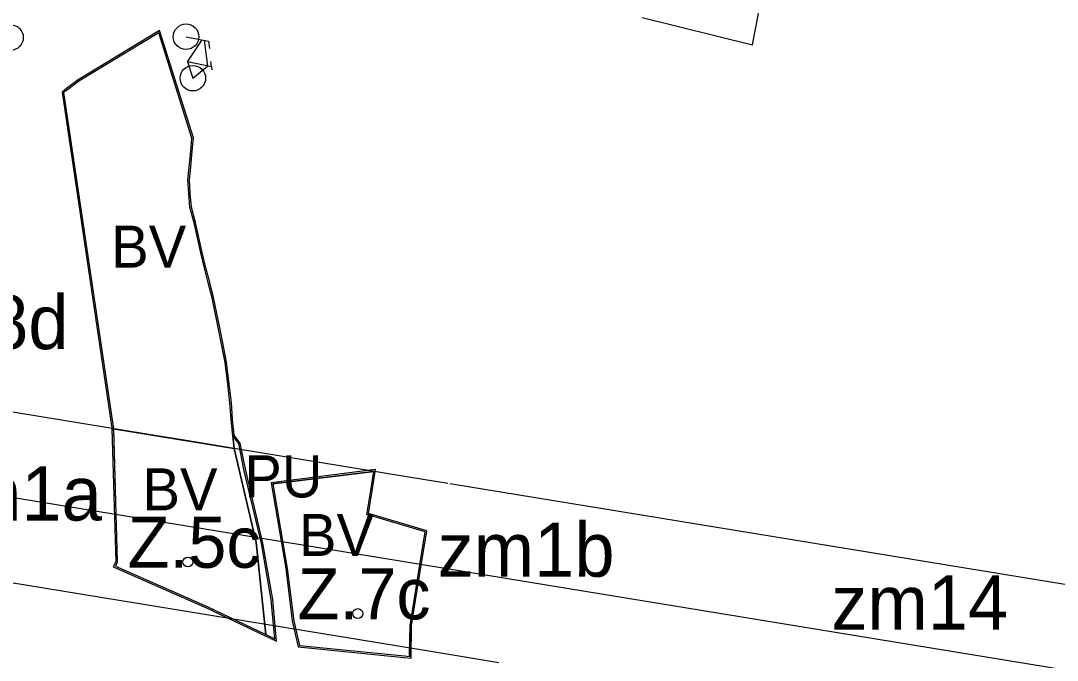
# Model space of a CAD drawing. Extents: x -555070 to -553076, y -1186731 to -1182766.
# Drawn here: x -554414.1 to -554069.4, y -1185567.7 to -1185354.8 of the extents above; entities that cross this region are included whole.
import ezdxf

# ---------------------------------------------------------------- set-up
doc = ezdxf.new("R2010")
doc.units = 0
for name, color, linetype in [('CYKLISTI_stav', 7, 'Continuous'), ('HRANICE_ZMENY_DO_KOO', 7, 'Continuous'), ('Level 10', 7, 'Continuous'), ('Level 13', 7, 'Continuous'), ('Level 29', 7, 'Continuous'), ('Level 4', 7, 'Continuous'), ('Level 46', 7, 'Continuous'), ('Level 52', 7, 'Continuous'), ('Level 56', 7, 'Continuous'), ('Level 58', 7, 'Continuous'), ('Level 59', 7, 'Continuous'), ('Level 63', 7, 'Continuous'), ('navrh_BV', 7, 'Continuous'), ('OBRYS_PLOCH', 7, 'Continuous'), ('stav_BV', 7, 'Continuous'), ('stav_PU', 7, 'Continuous'), ('ZU_plocha_aktualizace', 7, 'Continuous')]:
    doc.layers.add(name, color=color, linetype=linetype)

msp = doc.modelspace()

# ---------------------------------------------------------------- linework, layer by layer
at = {"layer": 'CYKLISTI_stav'}
msp.add_circle((-554417.54, -1185360.43), 4.25, dxfattribs=at)
at = {"layer": 'HRANICE_ZMENY_DO_KOO'}
for points in [[(-554343.11, -1185492.8), (-554343.66, -1185487.59), (-554344.1, -1185481.93), (-554344.79, -1185475.68), (-554345.66, -1185468.47), (-554347.53, -1185459.09), (-554350.01, -1185446.95), (-554351.29, -1185441.91), (-554352.54, -1185437.02), (-554353.81, -1185431.99), (-554355.99, -1185421.94), (-554357.37, -1185416.93), (-554357.74, -1185412.35), (-554358.05, -1185407.81), (-554357.6, -1185403.61), (-554357.23, -1185399.44), (-554356.73, -1185393.81), (-554367.98, -1185358.13), (-554395.09, -1185374.54), (-554398.94, -1185377.42), (-554400.4, -1185378.56), (-554383.76, -1185491.04)], [(-554383.82, -1185490.62), (-554382.57, -1185534.87), (-554383.35, -1185536.55), (-554352.18, -1185550.34), (-554329.03, -1185561.34), (-554330.35, -1185547.44), (-554333.58, -1185528.65), (-554339.41, -1185504.09), (-554341.19, -1185495.37), (-554343.11, -1185492.81)], [(-554383.68, -1185490.55), (-554343.14, -1185497.2), (-554343.59, -1185493)]]:
    msp.add_lwpolyline(points, dxfattribs=at)
msp.add_lwpolyline([(-554286.57, -1185566.73), (-554284.33, -1185566.95), (-554284.18, -1185556.14), (-554281.38, -1185538.8), (-554279.08, -1185524.56), (-554298.45, -1185518.79), (-554297.24, -1185511.26), (-554296.1, -1185504.23), (-554330.84, -1185508.57), (-554326.03, -1185537.16), (-554323.85, -1185554.59), (-554321.88, -1185563.24)], close=True, dxfattribs=at)
at = {"layer": 'Level 13'}
for p, q in [((-554207.47, -1185353.77), (-554170.79, -1185362.9)), ((-554368.27, -1185358.89), (-554394.81, -1185374.96)), ((-554357.24, -1185393.87), (-554368.27, -1185358.89)), ((-554170.79, -1185362.9), (-554170.79, -1185362.9)), ((-554394.81, -1185374.96), (-554398.64, -1185377.82)), ((-554398.64, -1185377.82), (-554399.87, -1185378.78)), ((-554399.87, -1185378.78), (-554383.32, -1185490.61)), ((-554357.73, -1185399.4), (-554357.24, -1185393.87)), ((-554358.1, -1185403.56), (-554357.73, -1185399.4)), ((-554358.55, -1185407.8), (-554358.1, -1185403.56)), ((-554358.24, -1185412.39), (-554358.55, -1185407.8)), ((-554357.86, -1185417.02), (-554358.24, -1185412.39)), ((-554356.48, -1185422.06), (-554357.86, -1185417.02)), ((-554355.39, -1185427.08), (-554356.48, -1185422.06)), ((-554354.3, -1185432.1), (-554355.39, -1185427.08)), ((-554353.02, -1185437.14), (-554354.3, -1185432.1)), ((-554351.77, -1185442.03), (-554353.02, -1185437.14)), ((-554345.29, -1185475.74), (-554346.15, -1185468.55)), ((-554344.6, -1185481.98), (-554345.29, -1185475.74)), ((-554344.16, -1185487.64), (-554344.6, -1185481.98)), ((-554343.59, -1185493), (-554344.16, -1185487.64)), ((-554371.71, -1185492.51), (-554383.32, -1185490.61)), ((-554383.32, -1185490.61), (-554383.32, -1185490.77)), ((-554383.32, -1185490.77), (-554382.97, -1185503.16)), ((-554361.11, -1185494.25), (-554371.71, -1185492.51)), ((-554343.14, -1185497.2), (-554343.59, -1185493)), ((-554341.66, -1185495.58), (-554343.59, -1185493)), ((-554343.59, -1185493), (-554343.14, -1185497.2)), ((-554343.14, -1185497.2), (-554361.11, -1185494.25)), ((-554339.9, -1185504.2), (-554341.66, -1185495.58)), ((-554382.97, -1185503.16), (-554382.85, -1185507.17)), ((-554334.07, -1185528.75), (-554339.9, -1185504.2)), ((-554296.7, -1185504.81), (-554330.26, -1185509)), ((-554297.73, -1185511.18), (-554296.7, -1185504.81)), ((-554382.85, -1185507.17), (-554382.74, -1185511.12)), ((-554330.26, -1185509), (-554325.54, -1185537.09)), ((-554382.74, -1185511.12), (-554382.63, -1185515.01)), ((-554299.01, -1185519.14), (-554297.73, -1185511.18)), ((-554382.63, -1185515.01), (-554382.41, -1185522.77)), ((-554279.64, -1185524.91), (-554299.01, -1185519.14)), ((-554382.41, -1185522.77), (-554382.3, -1185526.64)), ((-554382.3, -1185526.64), (-554382.2, -1185530.48)), ((-554281.87, -1185538.72), (-554279.64, -1185524.91)), ((-554382.2, -1185530.48), (-554382.07, -1185534.97)), ((-554330.85, -1185547.51), (-554334.07, -1185528.75)), ((-554382.07, -1185534.97), (-554382.68, -1185536.3)), ((-554325.54, -1185537.09), (-554323.36, -1185554.5)), ((-554284.68, -1185556.1), (-554281.87, -1185538.72)), ((-554329.61, -1185560.51), (-554330.85, -1185547.51)), ((-554323.36, -1185554.5), (-554321.47, -1185562.78)), ((-554284.82, -1185566.4), (-554284.68, -1185556.1)), ((-554332.6, -1185559.09), (-554329.61, -1185560.51)), ((-554321.47, -1185562.78), (-554286.52, -1185566.23)), ((-554286.52, -1185566.23), (-554284.82, -1185566.4))]:
    msp.add_line(p, q, dxfattribs=at)
for points in [[(-554170.79, -1185362.9), (-554170.35, -1185360.59), (-554167.01, -1185343.09)], [(-554346.15, -1185468.55), (-554348.02, -1185459.19), (-554350.5, -1185447.06), (-554351.77, -1185442.03)], [(-554383.32, -1185490.61), (-554371.71, -1185492.51), (-554343.14, -1185497.2)], [(-554382.68, -1185536.3), (-554351.97, -1185549.89), (-554332.6, -1185559.09)]]:
    msp.add_lwpolyline(points, dxfattribs=at)
at = {"layer": 'Level 29'}
for p, q in [((-554272.07, -1185508.85), (-554293.26, -1185505.38)), ((-554277.11, -1185564.77), (-554255.09, -1185568.38))]:
    msp.add_line(p, q, dxfattribs=at)
for points in [[(-554293.2, -1185505.39), (-554587.17, -1185457.18), (-554869.52, -1185410.99), (-555057.83, -1185309.87), (-555060.53, -1185308.42)], [(-555065.37, -1185337.55), (-554878.61, -1185437.76), (-554591.7, -1185484.82), (-554218.96, -1185545.93), (-553901.49, -1185597.94), (-553620.76, -1185643.99), (-553313.81, -1185694.25), (-553085.95, -1185731.63)], [(-555070.22, -1185366.68), (-555067.64, -1185368.06), (-554890.63, -1185462.96), (-554888.02, -1185464.13), (-554884.43, -1185465.07), (-554596.24, -1185512.45), (-554277.11, -1185564.77)], [(-553075.64, -1185704.95), (-553309.27, -1185666.62), (-553616.23, -1185616.35), (-553896.96, -1185570.3), (-554214.44, -1185518.3), (-554271.41, -1185508.96)]]:
    msp.add_lwpolyline(points, dxfattribs=at)
at = {"layer": 'Level 4'}
for centre in [(-554358.57, -1185534.95), (-554358.57, -1185534.95), (-554302.04, -1185552.12)]:
    msp.add_circle(centre, 1.64, dxfattribs=at)
at = {"layer": 'Level 52'}
msp.add_lwpolyline([(-554399.87, -1185378.78), (-554383.32, -1185490.61), (-554371.71, -1185492.51), (-554343.14, -1185497.2)], dxfattribs=at)
at = {"layer": 'Level 56'}
for p, q in [((-554371.71, -1185492.51), (-554383.32, -1185490.61)), ((-554361.11, -1185494.25), (-554371.71, -1185492.51)), ((-554343.14, -1185497.2), (-554361.11, -1185494.25)), ((-554335.87, -1185528.47), (-554343.14, -1185497.2)), ((-554382.97, -1185503.16), (-554382.85, -1185507.17)), ((-554296.7, -1185504.81), (-554330.26, -1185509)), ((-554297.73, -1185511.18), (-554296.7, -1185504.81)), ((-554382.85, -1185507.17), (-554382.74, -1185511.12)), ((-554330.26, -1185509), (-554325.54, -1185537.09)), ((-554382.74, -1185511.12), (-554382.63, -1185515.01)), ((-554299.01, -1185519.14), (-554297.73, -1185511.18)), ((-554382.63, -1185515.01), (-554382.41, -1185522.77)), ((-554279.64, -1185524.91), (-554299.01, -1185519.14)), ((-554382.41, -1185522.77), (-554382.3, -1185526.64)), ((-554382.3, -1185526.64), (-554382.2, -1185530.48)), ((-554281.87, -1185538.72), (-554279.64, -1185524.91)), ((-554382.2, -1185530.48), (-554382.07, -1185534.97)), ((-554332.6, -1185559.09), (-554335.87, -1185528.47)), ((-554325.54, -1185537.09), (-554323.36, -1185554.5)), ((-554284.68, -1185556.1), (-554281.87, -1185538.72)), ((-554351.97, -1185549.89), (-554332.6, -1185559.09)), ((-554323.36, -1185554.5), (-554321.47, -1185562.78)), ((-554284.82, -1185566.4), (-554284.68, -1185556.1)), ((-554321.47, -1185562.78), (-554286.52, -1185566.23)), ((-554286.52, -1185566.23), (-554284.82, -1185566.4))]:
    msp.add_line(p, q, dxfattribs=at)
for points in [[(-554383.32, -1185490.61), (-554383.32, -1185490.77), (-554382.97, -1185503.16)], [(-554382.07, -1185534.97), (-554382.68, -1185536.3), (-554351.97, -1185549.89)]]:
    msp.add_lwpolyline(points, dxfattribs=at)
at = {"layer": 'Level 58'}
for p, q in [((-554359.15, -1185360.16), (-554351.65, -1185361.64)), ((-554358.71, -1185368.52), (-554353.82, -1185361.21)), ((-554353.12, -1185361.34), (-554352.03, -1185369.92)), ((-554351.65, -1185361.64), (-554351.31, -1185364.06)), ((-554350.68, -1185370.21), (-554358.71, -1185368.52)), ((-554358.71, -1185368.52), (-554356.9, -1185373.97)), ((-554350.68, -1185370.21), (-554350.95, -1185368.41)), ((-554356.9, -1185373.97), (-554352.03, -1185369.92)), ((-554350.68, -1185370.21), (-554350.56, -1185371.2))]:
    msp.add_line(p, q, dxfattribs=at)
for centre in [(-554359.15, -1185360.16), (-554356.9, -1185373.97)]:
    msp.add_circle(centre, 4.25, dxfattribs=at)
at = {"layer": 'navrh_BV'}
for p, q in [((-554383.32, -1185490.61), (-554382.07, -1185534.97)), ((-554371.71, -1185492.51), (-554383.32, -1185490.61)), ((-554383.32, -1185490.61), (-554383.32, -1185490.77)), ((-554383.32, -1185490.77), (-554382.97, -1185503.16)), ((-554361.11, -1185494.25), (-554371.71, -1185492.51)), ((-554343.14, -1185497.2), (-554361.11, -1185494.25)), ((-554382.97, -1185503.16), (-554382.85, -1185507.17)), ((-554330.26, -1185509), (-554296.7, -1185504.81)), ((-554296.7, -1185504.81), (-554330.26, -1185509)), ((-554297.73, -1185511.18), (-554296.7, -1185504.81)), ((-554382.85, -1185507.17), (-554382.74, -1185511.12)), ((-554330.26, -1185509), (-554325.54, -1185537.09)), ((-554382.74, -1185511.12), (-554382.63, -1185515.01)), ((-554299.01, -1185519.14), (-554297.73, -1185511.18)), ((-554382.63, -1185515.01), (-554382.41, -1185522.77)), ((-554279.64, -1185524.91), (-554299.01, -1185519.14)), ((-554382.41, -1185522.77), (-554382.3, -1185526.64)), ((-554382.3, -1185526.64), (-554382.2, -1185530.48)), ((-554281.87, -1185538.72), (-554279.64, -1185524.91)), ((-554382.2, -1185530.48), (-554382.07, -1185534.97)), ((-554382.07, -1185534.97), (-554382.68, -1185536.3)), ((-554325.54, -1185537.09), (-554323.36, -1185554.5)), ((-554284.68, -1185556.1), (-554281.87, -1185538.72)), ((-554323.36, -1185554.5), (-554321.47, -1185562.78)), ((-554284.68, -1185556.1), (-554284.82, -1185566.4)), ((-554284.82, -1185566.4), (-554284.68, -1185556.1)), ((-554321.47, -1185562.78), (-554286.52, -1185566.23)), ((-554286.52, -1185566.23), (-554284.82, -1185566.4))]:
    msp.add_line(p, q, dxfattribs=at)
for points in [[(-554332.6, -1185559.09), (-554335.87, -1185528.47), (-554343.14, -1185497.2)], [(-554382.68, -1185536.3), (-554351.97, -1185549.89), (-554332.6, -1185559.09)]]:
    msp.add_lwpolyline(points, dxfattribs=at)
at = {"layer": 'OBRYS_PLOCH'}
for p, q in [((-554368.27, -1185358.89), (-554394.81, -1185374.96)), ((-554357.24, -1185393.87), (-554368.27, -1185358.89)), ((-554394.81, -1185374.96), (-554398.64, -1185377.82)), ((-554398.64, -1185377.82), (-554399.87, -1185378.78)), ((-554399.87, -1185378.78), (-554383.32, -1185490.61)), ((-554357.73, -1185399.4), (-554357.24, -1185393.87)), ((-554358.1, -1185403.56), (-554357.73, -1185399.4)), ((-554358.55, -1185407.8), (-554358.1, -1185403.56)), ((-554358.24, -1185412.39), (-554358.55, -1185407.8)), ((-554357.86, -1185417.02), (-554358.24, -1185412.39)), ((-554356.48, -1185422.06), (-554357.86, -1185417.02)), ((-554355.39, -1185427.08), (-554356.48, -1185422.06)), ((-554354.3, -1185432.1), (-554355.39, -1185427.08)), ((-554353.02, -1185437.14), (-554354.3, -1185432.1)), ((-554351.77, -1185442.03), (-554353.02, -1185437.14)), ((-554345.29, -1185475.74), (-554346.15, -1185468.55)), ((-554344.6, -1185481.98), (-554345.29, -1185475.74)), ((-554344.16, -1185487.64), (-554344.6, -1185481.98)), ((-554343.59, -1185493), (-554344.16, -1185487.64)), ((-554383.32, -1185490.61), (-554382.07, -1185534.97)), ((-554371.71, -1185492.51), (-554383.32, -1185490.61)), ((-554383.32, -1185490.61), (-554383.32, -1185490.77)), ((-554383.32, -1185490.77), (-554382.97, -1185503.16)), ((-554361.11, -1185494.25), (-554371.71, -1185492.51)), ((-554341.66, -1185495.58), (-554343.59, -1185493)), ((-554343.59, -1185493), (-554343.14, -1185497.2)), ((-554343.14, -1185497.2), (-554343.59, -1185493)), ((-554343.14, -1185497.2), (-554361.11, -1185494.25)), ((-554339.9, -1185504.2), (-554341.66, -1185495.58)), ((-554382.97, -1185503.16), (-554382.85, -1185507.17)), ((-554334.07, -1185528.75), (-554339.9, -1185504.2)), ((-554330.26, -1185509), (-554296.7, -1185504.81)), ((-554296.7, -1185504.81), (-554330.26, -1185509)), ((-554297.73, -1185511.18), (-554296.7, -1185504.81)), ((-554382.85, -1185507.17), (-554382.74, -1185511.12)), ((-554330.26, -1185509), (-554325.54, -1185537.09)), ((-554382.74, -1185511.12), (-554382.63, -1185515.01)), ((-554299.01, -1185519.14), (-554297.73, -1185511.18)), ((-554382.63, -1185515.01), (-554382.41, -1185522.77)), ((-554279.64, -1185524.91), (-554299.01, -1185519.14)), ((-554382.41, -1185522.77), (-554382.3, -1185526.64)), ((-554382.3, -1185526.64), (-554382.2, -1185530.48)), ((-554281.87, -1185538.72), (-554279.64, -1185524.91)), ((-554382.2, -1185530.48), (-554382.07, -1185534.97)), ((-554330.85, -1185547.51), (-554334.07, -1185528.75)), ((-554382.07, -1185534.97), (-554382.68, -1185536.3)), ((-554325.54, -1185537.09), (-554323.36, -1185554.5)), ((-554284.68, -1185556.1), (-554281.87, -1185538.72)), ((-554329.61, -1185560.51), (-554330.85, -1185547.51)), ((-554323.36, -1185554.5), (-554321.47, -1185562.78)), ((-554284.68, -1185556.1), (-554284.82, -1185566.4)), ((-554284.82, -1185566.4), (-554284.68, -1185556.1)), ((-554332.6, -1185559.09), (-554329.61, -1185560.51)), ((-554321.47, -1185562.78), (-554286.52, -1185566.23)), ((-554286.52, -1185566.23), (-554284.82, -1185566.4))]:
    msp.add_line(p, q, dxfattribs=at)
for points in [[(-554346.15, -1185468.55), (-554348.02, -1185459.19), (-554350.5, -1185447.06), (-554351.77, -1185442.03)], [(-554383.32, -1185490.61), (-554371.71, -1185492.51), (-554343.14, -1185497.2)], [(-554332.6, -1185559.09), (-554335.87, -1185528.47), (-554343.14, -1185497.2)], [(-554343.14, -1185497.2), (-554335.87, -1185528.47), (-554332.6, -1185559.09)], [(-554382.68, -1185536.3), (-554351.97, -1185549.89), (-554332.6, -1185559.09)]]:
    msp.add_lwpolyline(points, dxfattribs=at)
at = {"layer": 'stav_BV'}
for p, q in [((-554368.27, -1185358.89), (-554394.81, -1185374.96)), ((-554357.24, -1185393.87), (-554368.27, -1185358.89)), ((-554394.81, -1185374.96), (-554398.64, -1185377.82)), ((-554398.64, -1185377.82), (-554399.87, -1185378.78)), ((-554399.87, -1185378.78), (-554383.32, -1185490.61)), ((-554357.73, -1185399.4), (-554357.24, -1185393.87)), ((-554358.1, -1185403.56), (-554357.73, -1185399.4)), ((-554358.55, -1185407.8), (-554358.1, -1185403.56)), ((-554358.24, -1185412.39), (-554358.55, -1185407.8)), ((-554357.86, -1185417.02), (-554358.24, -1185412.39)), ((-554356.48, -1185422.06), (-554357.86, -1185417.02)), ((-554355.39, -1185427.08), (-554356.48, -1185422.06)), ((-554354.3, -1185432.1), (-554355.39, -1185427.08)), ((-554353.02, -1185437.14), (-554354.3, -1185432.1)), ((-554351.77, -1185442.03), (-554353.02, -1185437.14)), ((-554345.29, -1185475.74), (-554346.15, -1185468.55)), ((-554344.6, -1185481.98), (-554345.29, -1185475.74)), ((-554344.16, -1185487.64), (-554344.6, -1185481.98)), ((-554343.59, -1185493), (-554344.16, -1185487.64)), ((-554343.14, -1185497.2), (-554343.59, -1185493))]:
    msp.add_line(p, q, dxfattribs=at)
for points in [[(-554346.15, -1185468.55), (-554348.02, -1185459.19), (-554350.5, -1185447.06), (-554351.77, -1185442.03)], [(-554383.32, -1185490.61), (-554371.71, -1185492.51), (-554343.14, -1185497.2)]]:
    msp.add_lwpolyline(points, dxfattribs=at)
at = {"layer": 'stav_PU'}
for p, q in [((-554341.66, -1185495.58), (-554343.59, -1185493)), ((-554343.59, -1185493), (-554343.14, -1185497.2)), ((-554339.9, -1185504.2), (-554341.66, -1185495.58)), ((-554334.07, -1185528.75), (-554339.9, -1185504.2)), ((-554330.85, -1185547.51), (-554334.07, -1185528.75)), ((-554329.61, -1185560.51), (-554330.85, -1185547.51)), ((-554332.6, -1185559.09), (-554329.61, -1185560.51))]:
    msp.add_line(p, q, dxfattribs=at)
msp.add_lwpolyline([(-554343.14, -1185497.2), (-554335.87, -1185528.47), (-554332.6, -1185559.09)], dxfattribs=at)
at = {"layer": 'ZU_plocha_aktualizace'}
for p, q in [((-554368.27, -1185358.89), (-554394.81, -1185374.96)), ((-554357.24, -1185393.87), (-554368.27, -1185358.89)), ((-554394.81, -1185374.96), (-554398.64, -1185377.82)), ((-554398.64, -1185377.82), (-554399.87, -1185378.78)), ((-554399.87, -1185378.78), (-554383.32, -1185490.61)), ((-554357.73, -1185399.4), (-554357.24, -1185393.87)), ((-554358.1, -1185403.56), (-554357.73, -1185399.4)), ((-554358.55, -1185407.8), (-554358.1, -1185403.56)), ((-554358.24, -1185412.39), (-554358.55, -1185407.8)), ((-554357.86, -1185417.02), (-554358.24, -1185412.39)), ((-554356.48, -1185422.06), (-554357.86, -1185417.02)), ((-554355.39, -1185427.08), (-554356.48, -1185422.06)), ((-554354.3, -1185432.1), (-554355.39, -1185427.08)), ((-554353.02, -1185437.14), (-554354.3, -1185432.1)), ((-554351.77, -1185442.03), (-554353.02, -1185437.14)), ((-554345.29, -1185475.74), (-554346.15, -1185468.55)), ((-554344.6, -1185481.98), (-554345.29, -1185475.74)), ((-554344.16, -1185487.64), (-554344.6, -1185481.98)), ((-554343.59, -1185493), (-554344.16, -1185487.64)), ((-554383.32, -1185490.61), (-554371.71, -1185492.51)), ((-554371.71, -1185492.51), (-554343.14, -1185497.2)), ((-554343.14, -1185497.2), (-554343.59, -1185493))]:
    msp.add_line(p, q, dxfattribs=at)
msp.add_lwpolyline([(-554346.15, -1185468.55), (-554348.02, -1185459.19), (-554350.5, -1185447.06), (-554351.77, -1185442.03)], dxfattribs=at)

# ---------------------------------------------------------------- texts
at = {"layer": 'Level 10'}
for s, p in [('zm8d', (-554457.1, -1185464.13)), ('zm1a', (-554446.03, -1185521.16)), ('zm1b', (-554275.5, -1185539.86)), ('zm14', (-554144.57, -1185557.43))]:
    msp.add_text(s, height=18, dxfattribs=at).set_placement(p)
at = {"layer": 'Level 46'}
for s, p in [('Z.5c', (-554378.59, -1185536.89)), ('Z.7c', (-554322.06, -1185554.05))]:
    msp.add_text(s, height=17, dxfattribs=at).set_placement(p)
at = {"layer": 'Level 59'}
for s, p in [('BV', (-554384.06, -1185437.02)), ('PU', (-554339.79, -1185513.47))]:
    msp.add_text(s, height=14, dxfattribs=at).set_placement(p)
at = {"layer": 'Level 63'}
for p in [(-554373.66, -1185517.79), (-554321.61, -1185532.97)]:
    msp.add_text('BV', height=14, dxfattribs=at).set_placement(p)

doc.saveas('drawing.dxf')
